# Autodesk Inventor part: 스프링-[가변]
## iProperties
Created: 2014-12
Part Number: 스프링-[가변]
Document SubType Name: Modeling
Designer: elite
Density: 1 g/cm^3
Mass: 11.365 g
Surface Area: 115.211 cm^2
Volume: 11.365 cm^3
Author: elite
